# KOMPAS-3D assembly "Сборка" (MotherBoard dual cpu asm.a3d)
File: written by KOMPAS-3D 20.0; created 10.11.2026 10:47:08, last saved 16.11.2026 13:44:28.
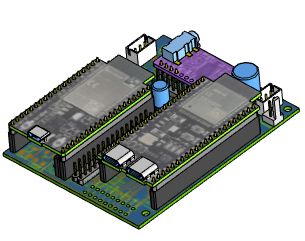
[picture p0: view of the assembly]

Document properties: Полное имя файла: D:\RicWork\Project-EPS32\box_compas\сборки компонентов\MotherBoard dual cpu asm.a3d

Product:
- Part/product: Сборка
    Масса: 0.183959
  - Component [assembly]: Сборка  | Масса: 0.00967177; source file: ..\цап ацп\pcm5102A_asm_pj.a3d
  - Component [detail]: Деталь  | source file: Деталь.m3d
  - Component [assembly]: Сборка  | Масса: 0.0330708; source file: ..\esp32\esp32-wrover-n8r8 38pin_asm+.a3d
  - Component [detail]: Деталь  | qty 2  | Масса: 0.00102673; source file: ..\разъемы\pls_8.m3d
  - Component [detail]: Деталь  | Масса: 0.00141779; source file: ..\разъемы\pls_11.m3d
  - Component [assembly]: Сборка  | Масса: 0.0102229; source file: ..\цап ацп\pcm5102A_asm+ 5pin.a3d
  - Component [detail]: Деталь  | Масса: 0.00577391; source file: ..\разъемы\pbs_19.m3d
  - Component [detail]: Деталь  | Масса: 0.0646786; source file: ..\esp32\pcb x2 esp32 v2.m3d
  - Component [detail]: Деталь  | Масса: 0.000929543; source file: ..\разъемы\WF-2 (DS1070-2 M).m3d
  - Component [detail]: Деталь  | qty 2  | Масса: 0.00117184; source file: ..\разъемы\B3B-XH-A.m3d
  - Component [detail]: Деталь  | qty 2  | Масса: 0.000635679; source file: ..\разъемы\pls_5.m3d
  - Component [detail]: Деталь  | qty 3  | Масса: 0.000244624; source file: ..\разъемы\pls_2.m3d
  - Component [detail]: Деталь  | Масса: 0.000374976; source file: ..\разъемы\pls_3.m3d
  - Component [assembly]: Сборка  | Масса: 0.0411431; source file: ..\esp32\esp32-s3-n16r8 44pin_asm+.a3d
  - Component [detail]: Деталь  | Масса: 0.0076211; source file: ..\прочее\1000mkf 10x12.5 p5 (10ZLH1000MEFC10x12.5 (К50-35).m3d
  - Component [detail]: Деталь  | Масса: 0.00265163; source file: ..\прочее\470mkf 6.3x11 p2.5 (10YXJ470M6.3X11 (К50-35 имп.)).m3d

Referenced files in D:\RicWork\Project-EPS32\box_compas\разъемы\: pbs_19.m3d, B3B-XH-A.m3d, WF-2 (DS1070-2 M).m3d, pls_5.m3d, pls_2.m3d, pls_3.m3d, pls_8.m3d, pls_11.m3d
Referenced files in D:\RicWork\Project-EPS32\box_compas\цап ацп\: pcm5102A_asm+ 5pin.a3d, pcm5102A_asm_pj.a3d
Referenced files in D:\RicWork\Project-EPS32\box_compas\esp32\: pcb x2 esp32 v2.m3d, esp32-s3-n16r8 44pin_asm+.a3d, esp32-wrover-n8r8 38pin_asm+.a3d
Referenced files in D:\RicWork\Project-EPS32\box_compas\сборки компонентов\: Деталь.m3d
Referenced files in D:\RicWork\Project-EPS32\box_compas\прочее\: 1000mkf 10x12.5 p5 (10ZLH1000MEFC10x12.5 (К50-35).m3d, 470mkf 6.3x11 p2.5 (10YXJ470M6.3X11 (К50-35 имп.)).m3d
Referenced files in D:\myProjects\Progect_esp32\box_compas\разъемы\: B3B-XH-A.m3d, pls_5.m3d, pls_2.m3d, pls_8.m3d
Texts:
  Деталь (1)
  Деталь (2)
  Деталь (3)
